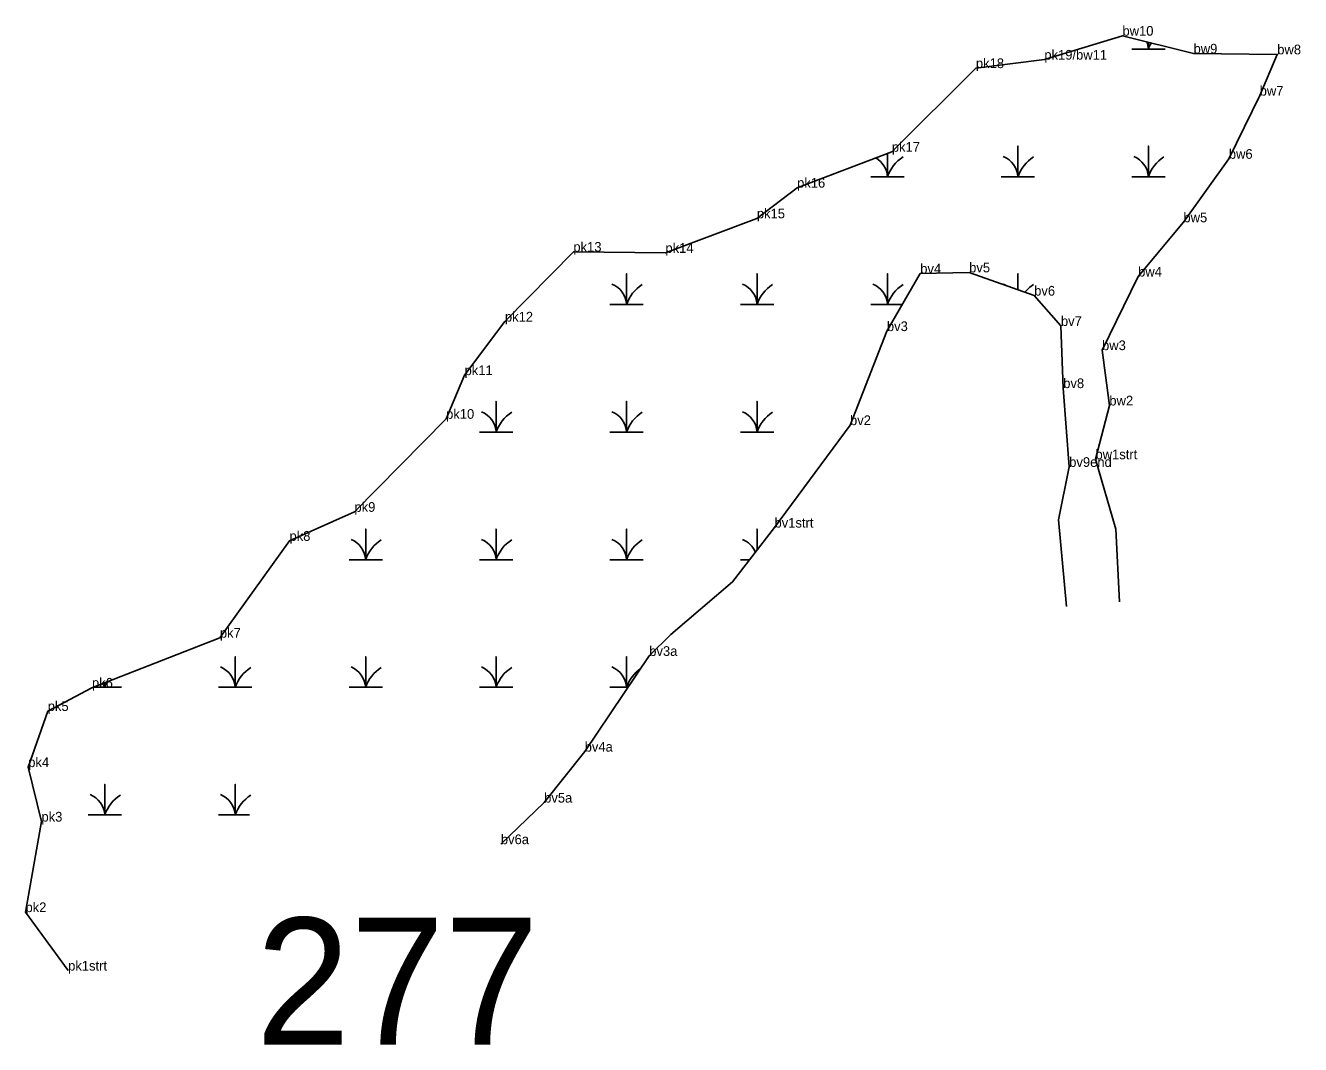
# Model space of a CAD drawing. Extents: x 2072529 to 2268796, y 436423 to 470406.
# Drawn here: x 2236884 to 2237542, y 437884 to 438409 of the extents above; entities that cross this region are included whole.
import ezdxf

# ---------------------------------------------------------------- set-up
doc = ezdxf.new("R2010")
doc.units = 0
for name, color, linetype in [('Default', 7, 'Continuous'), ('Exist Environmental Wetland Boundary', 7, 'Continuous'), ('Exist Environmental Wetland Boundary Cogo Comment', 7, 'Continuous'), ('Exist Hydro Swamp or Marsh', 7, 'Continuous'), ('Old_Level_20', 7, 'Continuous')]:
    doc.layers.add(name, color=color, linetype=linetype)

msp = doc.modelspace()

# ---------------------------------------------------------------- linework, layer by layer
at = {"layer": 'Exist Environmental Wetland Boundary'}
for points in [[(2236906.29, 437922.22), (2236884.32, 437952.37), (2236892.56, 437999.04), (2236885.73, 438027.14), (2236895.79, 438056.04), (2236918.59, 438068.08), (2236984.53, 438093.85), (2237020.42, 438143.77), (2237053.91, 438158.73), (2237101.15, 438206.69), (2237110.68, 438229.19), (2237131.48, 438256.81), (2237166.77, 438292.82), (2237214.22, 438292.24), (2237261.36, 438310.02), (2237282.1, 438325.83), (2237330.94, 438344.34), (2237374.28, 438387.48), (2237409.56, 438391.84), (2237449.83, 438404.18), (2237486.49, 438394.98), (2237529.64, 438394.57), (2237520.58, 438373.28), (2237504.68, 438340.72), (2237481.26, 438308), (2237457.91, 438280.03), (2237439.31, 438242.09), (2237443.08, 438213.57), (2237435.93, 438185.84), (2237446.36, 438149.85), (2237448.36, 438112.41)], [(2237421.03, 438109.87), (2237416.87, 438154.61), (2237422.38, 438181.89), (2237419.3, 438222.51), (2237418.11, 438254.56), (2237404.32, 438270.18), (2237370.8, 438282.17), (2237345.58, 438281.58), (2237328.4, 438251.91), (2237309.38, 438203.42), (2237270.46, 438150.61), (2237248.85, 438122.61), (2237217.02, 438095.45)], [(2237129.39, 437987.4), (2237151.7, 438008.83), (2237172.59, 438035.11), (2237205.88, 438084.44), (2237217.02, 438095.45)]]:
    msp.add_lwpolyline(points, dxfattribs=at)
at = {"layer": 'Exist Hydro Swamp or Marsh'}
for points in [[(2237454.61, 438397.26), (2237463.21, 438397.26), (2237463.21, 438400.82)], [(2237463.21, 438400.82), (2237463.21, 438397.26), (2237471.81, 438397.26)], [(2237320.11, 438331.46), (2237328.71, 438331.46), (2237328.71, 438343.49)], [(2237328.71, 438343.49), (2237328.71, 438331.46), (2237337.31, 438331.46)], [(2237387.36, 438331.46), (2237395.96, 438331.46), (2237395.96, 438347.24), (2237395.96, 438331.46), (2237404.56, 438331.46)], [(2237454.61, 438331.46), (2237463.21, 438331.46), (2237463.21, 438347.24), (2237463.21, 438331.46), (2237471.81, 438331.46)], [(2237185.61, 438265.66), (2237194.21, 438265.66), (2237194.21, 438281.44), (2237194.21, 438265.66), (2237202.81, 438265.66)], [(2237252.86, 438265.66), (2237261.46, 438265.66), (2237261.46, 438281.44), (2237261.46, 438265.66), (2237270.06, 438265.66)], [(2237320.11, 438265.66), (2237328.71, 438265.66), (2237328.71, 438281.44), (2237328.71, 438265.66), (2237336.36, 438265.66)], [(2237395.96, 438273.17), (2237395.96, 438281.44), (2237395.96, 438273.17)], [(2237118.36, 438199.86), (2237126.96, 438199.86), (2237126.96, 438215.64), (2237126.96, 438199.86), (2237135.56, 438199.86)], [(2237185.61, 438199.86), (2237194.21, 438199.86), (2237194.21, 438215.64), (2237194.21, 438199.86), (2237202.81, 438199.86)], [(2237252.86, 438199.86), (2237261.46, 438199.86), (2237261.46, 438215.64), (2237261.46, 438199.86), (2237270.06, 438199.86)], [(2237051.11, 438134.06), (2237059.71, 438134.06), (2237059.71, 438149.84), (2237059.71, 438134.06), (2237068.31, 438134.06)], [(2237118.36, 438134.06), (2237126.96, 438134.06), (2237126.96, 438149.84), (2237126.96, 438134.06), (2237135.56, 438134.06)], [(2237185.61, 438134.06), (2237194.21, 438134.06), (2237194.21, 438149.84), (2237194.21, 438134.06), (2237202.81, 438134.06)], [(2237261.46, 438138.95), (2237261.46, 438149.84), (2237261.46, 438138.95)], [(2237252.86, 438134.06), (2237257.68, 438134.06)], [(2236983.86, 438068.26), (2236992.46, 438068.26), (2236992.46, 438084.04), (2236992.46, 438068.26), (2237001.06, 438068.26)], [(2237051.11, 438068.26), (2237059.71, 438068.26), (2237059.71, 438084.04), (2237059.71, 438068.26), (2237068.31, 438068.26)], [(2237118.36, 438068.26), (2237126.96, 438068.26), (2237126.96, 438084.04), (2237126.96, 438068.26), (2237135.56, 438068.26)], [(2237185.61, 438068.26), (2237194.21, 438068.26), (2237194.21, 438084.04), (2237194.21, 438068.26), (2237194.96, 438068.26)], [(2236919.03, 438068.26), (2236925.21, 438068.26), (2236925.21, 438070.67)], [(2236925.21, 438070.67), (2236925.21, 438068.26), (2236933.81, 438068.26)], [(2236916.61, 438002.46), (2236925.21, 438002.46), (2236925.21, 438018.24), (2236925.21, 438002.46), (2236933.81, 438002.46)], [(2236983.86, 438002.46), (2236992.46, 438002.46), (2236992.46, 438018.24), (2236992.46, 438002.46), (2236999.72, 438002.46)]]:
    msp.add_lwpolyline(points, dxfattribs=at)
for centre, radius, start, end in [((2237450.95, 438396.37), 12.3, 4.14034, 22.34613), ((2237481.45, 438391.2), 19.22, 151.15835, 161.62219), ((2237316.45, 438330.57), 12.3, 4.14034, 59.73532), ((2237346.95, 438325.4), 19.22, 122.12745, 161.62219), ((2237383.7, 438330.57), 12.3, 4.14034, 67.53497), ((2237414.2, 438325.4), 19.22, 122.12745, 161.62219), ((2237450.95, 438330.57), 12.3, 4.14034, 67.53497), ((2237481.45, 438325.4), 19.22, 122.12745, 161.62219), ((2237181.95, 438264.77), 12.3, 4.14034, 67.53497), ((2237212.45, 438259.6), 19.22, 122.12745, 161.62219), ((2237249.2, 438264.77), 12.3, 4.14034, 67.53497), ((2237279.7, 438259.6), 19.22, 122.12745, 161.62219), ((2237316.45, 438264.77), 12.3, 4.14034, 67.53497), ((2237346.95, 438259.6), 19.22, 122.12745, 161.62219), ((2237383.7, 438264.77), 12.3, 58.60834, 67.53497), ((2237414.2, 438259.6), 19.22, 122.12745, 140.11258), ((2237450.95, 438264.77), 12.3, 66.0333, 67.53497), ((2237114.7, 438198.97), 12.3, 4.14034, 67.53497), ((2237145.2, 438193.8), 19.22, 122.12745, 161.62219), ((2237181.95, 438198.97), 12.3, 4.14034, 67.53497), ((2237212.45, 438193.8), 19.22, 122.12745, 161.62219), ((2237249.2, 438198.97), 12.3, 4.14034, 67.53497), ((2237279.7, 438193.8), 19.22, 122.12745, 161.62219), ((2237047.45, 438133.17), 12.3, 4.14034, 67.53497), ((2237077.95, 438128), 19.22, 122.12745, 161.62219), ((2237114.7, 438133.17), 12.3, 4.14034, 67.53497), ((2237145.2, 438128), 19.22, 122.12745, 161.62219), ((2237181.95, 438133.17), 12.3, 4.14034, 67.53497), ((2237212.45, 438128), 19.22, 122.12745, 161.62219), ((2237249.2, 438133.17), 12.3, 22.19282, 67.53497), ((2236980.2, 438067.37), 12.3, 4.14034, 67.53497), ((2237010.7, 438062.2), 19.22, 122.12745, 161.62219), ((2237047.45, 438067.37), 12.3, 4.14034, 67.53497), ((2237077.95, 438062.2), 19.22, 122.12745, 161.62219), ((2237114.7, 438067.37), 12.3, 4.14034, 67.53497), ((2237145.2, 438062.2), 19.22, 122.12745, 161.62219), ((2237181.95, 438067.37), 12.3, 4.14034, 67.53497), ((2237212.45, 438062.2), 19.22, 124.53396, 161.62219), ((2236912.95, 438067.37), 12.3, 4.14034, 14.85766), ((2236943.45, 438062.2), 19.22, 152.2304, 161.62219), ((2236912.95, 438001.57), 12.3, 4.14034, 67.53497), ((2236943.45, 437996.4), 19.22, 122.12745, 161.62219), ((2236980.2, 438001.57), 12.3, 4.14034, 67.53497), ((2237010.7, 437996.4), 19.22, 122.12745, 161.62219)]:
    msp.add_arc(centre, radius, start, end, dxfattribs=at)
at = {"layer": 'Old_Level_20'}
for p, q in [((2237449.83, 438404.18), (2237449.83, 438404.18)), ((2237409.56, 438391.84), (2237409.56, 438391.84)), ((2237486.49, 438394.98), (2237486.49, 438394.98)), ((2237529.64, 438394.57), (2237529.64, 438394.57)), ((2237374.28, 438387.48), (2237374.28, 438387.48)), ((2237520.58, 438373.28), (2237520.58, 438373.28)), ((2237330.94, 438344.34), (2237330.94, 438344.34)), ((2237504.68, 438340.72), (2237504.68, 438340.72)), ((2237282.1, 438325.83), (2237282.1, 438325.83)), ((2237261.36, 438310.02), (2237261.36, 438310.02)), ((2237481.26, 438308), (2237481.26, 438308)), ((2237166.77, 438292.82), (2237166.77, 438292.82)), ((2237214.22, 438292.24), (2237214.22, 438292.24)), ((2237345.58, 438281.58), (2237345.58, 438281.58)), ((2237370.8, 438282.17), (2237370.8, 438282.17)), ((2237457.91, 438280.03), (2237457.91, 438280.03)), ((2237404.32, 438270.18), (2237404.32, 438270.18)), ((2237131.48, 438256.81), (2237131.48, 438256.81)), ((2237328.4, 438251.91), (2237328.4, 438251.91)), ((2237418.11, 438254.56), (2237418.11, 438254.56)), ((2237439.31, 438242.09), (2237439.31, 438242.09)), ((2237110.68, 438229.19), (2237110.68, 438229.19)), ((2237419.3, 438222.51), (2237419.3, 438222.51)), ((2237443.08, 438213.57), (2237443.08, 438213.57)), ((2237101.15, 438206.69), (2237101.15, 438206.69)), ((2237309.38, 438203.42), (2237309.38, 438203.42)), ((2237435.93, 438185.84), (2237435.93, 438185.84)), ((2237422.38, 438181.89), (2237422.38, 438181.89)), ((2237053.91, 438158.73), (2237053.91, 438158.73)), ((2237270.46, 438150.61), (2237270.46, 438150.61)), ((2237020.42, 438143.77), (2237020.42, 438143.77)), ((2236984.53, 438093.85), (2236984.53, 438093.85)), ((2237205.88, 438084.44), (2237205.88, 438084.44)), ((2236918.59, 438068.08), (2236918.59, 438068.08)), ((2236895.79, 438056.04), (2236895.79, 438056.04)), ((2237172.59, 438035.11), (2237172.59, 438035.11)), ((2236885.73, 438027.14), (2236885.73, 438027.14)), ((2237151.7, 438008.83), (2237151.7, 438008.83)), ((2236892.56, 437999.04), (2236892.56, 437999.04)), ((2237129.39, 437987.4), (2237129.39, 437987.4)), ((2236884.32, 437952.37), (2236884.32, 437952.37)), ((2236906.29, 437922.22), (2236906.29, 437922.22))]:
    msp.add_line(p, q, dxfattribs=at)

# ---------------------------------------------------------------- texts
at = {"layer": 'Default'}
msp.add_text('277', height=65.34, dxfattribs=at).set_placement((2237003.11, 437884.12))
at = {"layer": 'Exist Environmental Wetland Boundary Cogo Comment'}
for s, p in [('bw10', (2237449.83, 438404.18)), ('pk19/bw11', (2237409.56, 438391.84)), ('bw9', (2237486.49, 438394.98)), ('bw8', (2237529.64, 438394.57)), ('pk18', (2237374.28, 438387.48)), ('bw7', (2237520.58, 438373.28)), ('pk17', (2237330.94, 438344.34)), ('bw6', (2237504.68, 438340.72)), ('pk16', (2237282.1, 438325.83)), ('pk15', (2237261.36, 438310.02)), ('bw5', (2237481.26, 438308)), ('pk13', (2237166.77, 438292.82)), ('pk14', (2237214.22, 438292.24)), ('bv4', (2237345.58, 438281.58)), ('bv5', (2237370.8, 438282.17)), ('bw4', (2237457.91, 438280.03)), ('bv6', (2237404.32, 438270.18)), ('pk12', (2237131.48, 438256.81)), ('bv7', (2237418.11, 438254.56)), ('bv3', (2237328.4, 438251.91)), ('bw3', (2237439.31, 438242.09)), ('pk11', (2237110.68, 438229.19)), ('bv8', (2237419.3, 438222.51)), ('bw2', (2237443.08, 438213.57)), ('pk10', (2237101.15, 438206.69)), ('bv2', (2237309.38, 438203.42)), ('bv9end', (2237422.38, 438181.89)), ('bw1strt', (2237435.93, 438185.84)), ('pk9', (2237053.91, 438158.73)), ('bv1strt', (2237270.46, 438150.61)), ('pk8', (2237020.42, 438143.77)), ('pk7', (2236984.53, 438093.85)), ('bv3a', (2237205.88, 438084.44)), ('pk6', (2236918.59, 438068.08)), ('pk5', (2236895.79, 438056.04)), ('bv4a', (2237172.59, 438035.11)), ('pk4', (2236885.73, 438027.14)), ('bv5a', (2237151.7, 438008.83)), ('pk3', (2236892.56, 437999.04)), ('bv6a', (2237129.39, 437987.4)), ('pk2', (2236884.32, 437952.37)), ('pk1strt', (2236906.29, 437922.22))]:
    msp.add_text(s, height=5, dxfattribs=at).set_placement(p)

doc.saveas('drawing.dxf')
